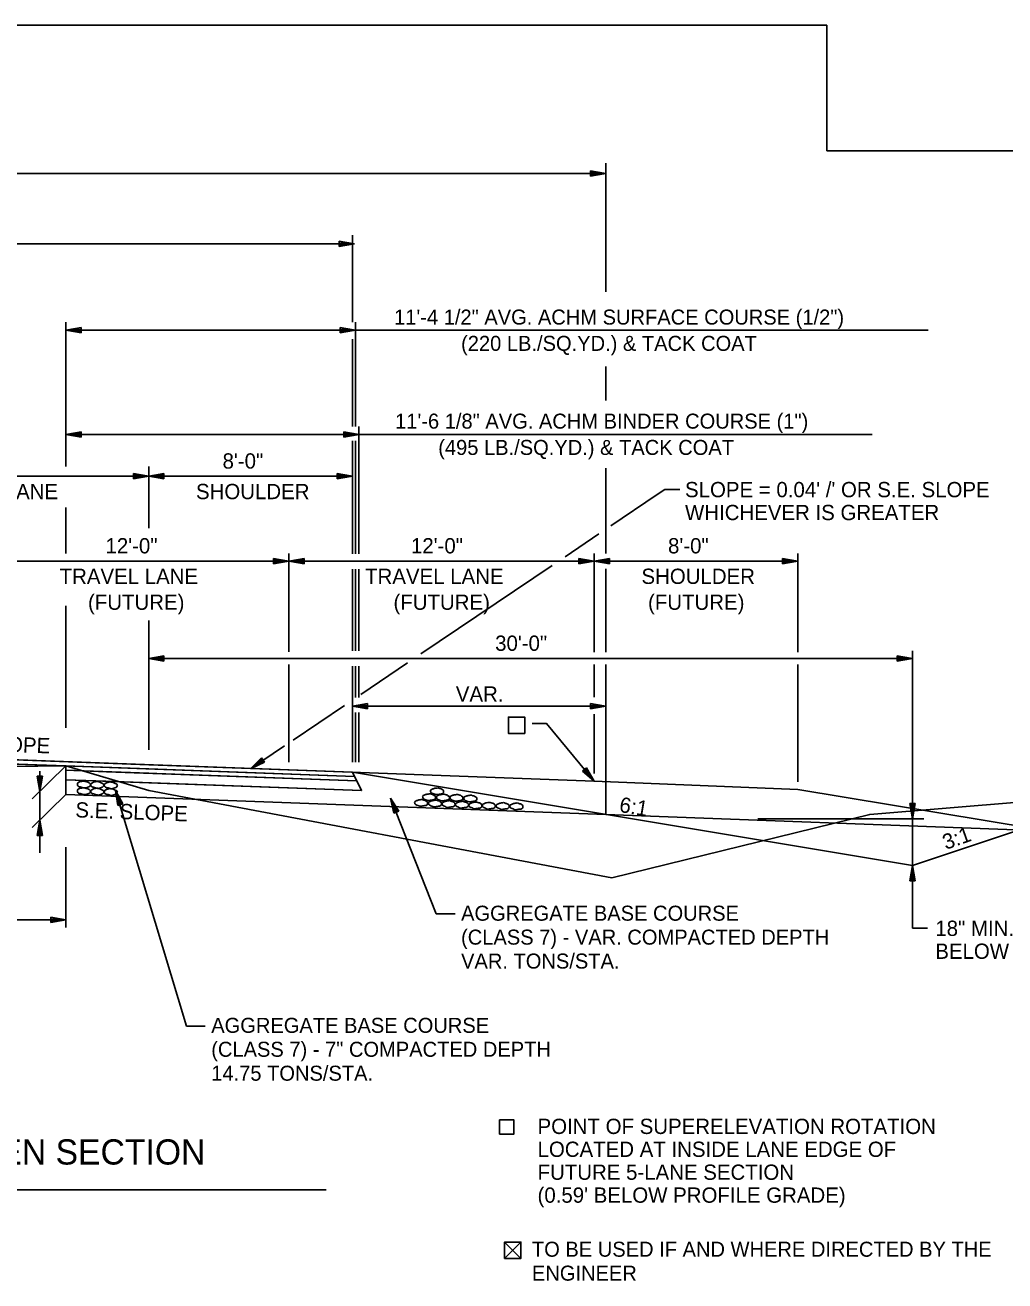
# Model space of a CAD drawing. Extents: x 1461846 to 1462006, y 1686171 to 1686805.
# Drawn here: x 1461933.27 to 1461971.75, y 1686623.62 to 1686672.94 of the extents above; entities that cross this region are included whole.
import ezdxf

# ---------------------------------------------------------------- set-up
doc = ezdxf.new("R2010")
doc.units = 0
for name, color, linetype in [('1', 7, 'Continuous'), ('10', 7, 'Continuous'), ('12', 7, 'Continuous'), ('19', 7, 'Continuous'), ('20', 7, 'Continuous'), ('3', 7, 'Continuous'), ('42', 7, 'Continuous'), ('Level 9', 7, 'Continuous'), ('R_Draft', 7, 'Continuous')]:
    doc.layers.add(name, color=color, linetype=linetype)

# ---------------------------------------------------------------- blocks, each defined once
blk = doc.blocks.new('ROCKS')
at = {"layer": '1'}
blk.add_spline([(0.013, 0.06), (0.053, 0.053), (0.107, 0.033), (0.133, 0.013), (0.133, -0.007), (0.12, -0.033), (0.107, -0.04), (0.073, -0.053), (0.033, -0.067), (0.013, -0.067), (-0.02, -0.06), (-0.06, -0.053), (-0.087, -0.047), (-0.113, -0.02), (-0.113, -0.007), (-0.107, 0.02), (-0.087, 0.033), (-0.067, 0.047), (-0.033, 0.053), (-0.02, 0.06), (0.013, 0.06)], degree=3, dxfattribs=at)

msp = doc.modelspace()

# ---------------------------------------------------------------- linework, layer by layer
at = {"layer": '10'}
for p, q in [((1461964.759, 1686672.939), (1461846.353, 1686672.939)), ((1461964.759, 1686667.999), (1461964.759, 1686672.939)), ((1461984.339, 1686667.999), (1461964.759, 1686667.999)), ((1461952.102, 1686625.138), (1461952.743, 1686624.497)), ((1461952.743, 1686625.138), (1461952.102, 1686624.497))]:
    msp.add_line(p, q, dxfattribs=at)
msp.add_lwpolyline([(1461952.253, 1686645.118), (1461952.894, 1686645.118), (1461952.894, 1686645.76), (1461952.253, 1686645.76)], close=True, dxfattribs=at)
for points in [[(1461951.906, 1686629.38), (1461951.906, 1686629.94), (1461952.466, 1686629.94), (1461952.466, 1686629.38), (1461951.906, 1686629.38)], [(1461952.495, 1686624.497), (1461952.743, 1686624.497), (1461952.743, 1686625.138), (1461952.102, 1686625.138), (1461952.102, 1686624.497), (1461952.483, 1686624.497)]]:
    msp.add_lwpolyline(points, dxfattribs=at)
at = {"layer": '19'}
for p, q in [((1461958.101, 1686654.5), (1461956.279, 1686653.272)), ((1461958.391, 1686654.696), (1461958.101, 1686654.5)), ((1461958.991, 1686654.696), (1461958.391, 1686654.696)), ((1461955.807, 1686652.955), (1461954.481, 1686652.06)), ((1461953.968, 1686651.715), (1461948.817, 1686648.242)), ((1461938.121, 1686648.063), (1461938.721, 1686648.168)), ((1461968.121, 1686648.063), (1461938.121, 1686648.063)), ((1461938.721, 1686647.958), (1461938.121, 1686648.063)), ((1461938.281, 1686648.078), (1461938.721, 1686648.113)), ((1461938.721, 1686648.008), (1461938.281, 1686648.048)), ((1461938.721, 1686648.168), (1461938.721, 1686647.958)), ((1461948.293, 1686647.889), (1461946.448, 1686646.645)), ((1461967.521, 1686647.958), (1461967.521, 1686648.168)), ((1461967.521, 1686648.168), (1461968.121, 1686648.063)), ((1461967.521, 1686648.113), (1461967.961, 1686648.078)), ((1461968.121, 1686648.063), (1461967.521, 1686647.958)), ((1461967.961, 1686648.048), (1461967.521, 1686648.008)), ((1461945.809, 1686646.214), (1461943.796, 1686644.858)), ((1461943.461, 1686644.632), (1461942.121, 1686643.728)), ((1461938.121, 1686643.888), (1461926.121, 1686644.332)), ((1461938.121, 1686643.722), (1461926.121, 1686644.166)), ((1461942.121, 1686643.728), (1461942.553, 1686644.157)), ((1461942.673, 1686643.985), (1461942.121, 1686643.728)), ((1461942.244, 1686643.832), (1461942.582, 1686644.116)), ((1461942.642, 1686644.03), (1461942.261, 1686643.807)), ((1461942.553, 1686644.157), (1461942.673, 1686643.985)), ((1461933.952, 1686643.44), (1461933.742, 1686643.44)), ((1461933.742, 1686643.44), (1461933.847, 1686642.84)), ((1461933.797, 1686643.44), (1461933.832, 1686643)), ((1461933.847, 1686642.84), (1461933.952, 1686643.44)), ((1461933.862, 1686643), (1461933.902, 1686643.44)), ((1461938.121, 1686643.722), (1461934.121, 1686643.87)), ((1461934.871, 1686642.717), (1461934.871, 1686643.842)), ((1461938.121, 1686643.555), (1461934.871, 1686643.675)), ((1461934.871, 1686643.675), (1461934.871, 1686643.3)), ((1461938.121, 1686643.888), (1461946.121, 1686643.592)), ((1461938.121, 1686643.722), (1461946.206, 1686643.422)), ((1461938.121, 1686643.555), (1461938.291, 1686643.549)), ((1461938.291, 1686643.549), (1461946.291, 1686643.253)), ((1461946.121, 1686643.592), (1461968.121, 1686639.926)), ((1461946.121, 1686643.592), (1461946.482, 1686642.871)), ((1461955.323, 1686643.772), (1461955.161, 1686643.639)), ((1461955.161, 1686643.639), (1461955.621, 1686643.241)), ((1461955.199, 1686643.666), (1461955.508, 1686643.356)), ((1461955.529, 1686643.37), (1461955.284, 1686643.734)), ((1461955.621, 1686643.241), (1461955.323, 1686643.772)), ((1461938.121, 1686643.18), (1461934.871, 1686643.3)), ((1461938.121, 1686643.18), (1461938.482, 1686643.167)), ((1461938.482, 1686643.167), (1461946.482, 1686642.871)), ((1461946.482, 1686642.871), (1461946.291, 1686643.253)), ((1461946.291, 1686643.253), (1461946.291, 1686643.253)), ((1461963.621, 1686642.921), (1461955.621, 1686643.241)), ((1461985.621, 1686639.254), (1461963.621, 1686642.921)), ((1461934.871, 1686642.717), (1461956.082, 1686641.932)), ((1461939.601, 1686633.623), (1461936.813, 1686642.882)), ((1461936.906, 1686642.282), (1461936.813, 1686642.882)), ((1461936.813, 1686642.882), (1461937.105, 1686642.347)), ((1461936.953, 1686642.298), (1461936.849, 1686642.726)), ((1461936.876, 1686642.736), (1461937.053, 1686642.333)), ((1461946.482, 1686642.871), (1461946.482, 1686642.871)), ((1461949.416, 1686638.029), (1461947.625, 1686642.581)), ((1461947.746, 1686641.986), (1461947.625, 1686642.581)), ((1461947.625, 1686642.581), (1461947.941, 1686642.061)), ((1461947.792, 1686642.005), (1461947.668, 1686642.427)), ((1461947.694, 1686642.438), (1461947.89, 1686642.044)), ((1461975.9, 1686642.519), (1461968.121, 1686639.926)), ((1461937.105, 1686642.347), (1461936.906, 1686642.282)), ((1461947.941, 1686642.061), (1461947.746, 1686641.986)), ((1461956.082, 1686641.932), (1461973.397, 1686641.291)), ((1461968.226, 1686642.37), (1461968.016, 1686642.37)), ((1461968.016, 1686642.37), (1461968.121, 1686641.77)), ((1461968.066, 1686642.37), (1461968.106, 1686641.93)), ((1461968.121, 1686641.77), (1461968.226, 1686642.37)), ((1461968.136, 1686641.93), (1461968.171, 1686642.37)), ((1461933.847, 1686641.715), (1461933.742, 1686641.115)), ((1461933.832, 1686641.555), (1461933.792, 1686641.115)), ((1461933.952, 1686641.115), (1461933.847, 1686641.715)), ((1461933.897, 1686641.115), (1461933.862, 1686641.555)), ((1461962.045, 1686641.77), (1461968.574, 1686641.77)), ((1461933.742, 1686641.115), (1461933.952, 1686641.115)), ((1461968.121, 1686639.926), (1461968.016, 1686639.326)), ((1461968.106, 1686639.766), (1461968.071, 1686639.326)), ((1461968.226, 1686639.326), (1461968.121, 1686639.926)), ((1461968.176, 1686639.326), (1461968.136, 1686639.766)), ((1461968.016, 1686639.326), (1461968.226, 1686639.326)), ((1461950.153, 1686638.029), (1461949.416, 1686638.029)), ((1461968.721, 1686637.465), (1461968.121, 1686637.465)), ((1461940.338, 1686633.623), (1461939.601, 1686633.623))]:
    msp.add_line(p, q, dxfattribs=at)
for points in [[(1461955.621, 1686643.241), (1461896.621, 1686645.424)], [(1461946.291, 1686643.253), (1461946.291, 1686643.253), (1461946.291, 1686643.253), (1461936.456, 1686643.616), (1461934.871, 1686643.675)], [(1461934.871, 1686643.3), (1461936.434, 1686643.242), (1461946.482, 1686642.871), (1461946.482, 1686642.871), (1461946.482, 1686642.871)]]:
    msp.add_lwpolyline(points, dxfattribs=at)
for points in [[(1461906.039, 1686644.909), (1461909.845, 1686644.768), (1461946.206, 1686643.422), (1461946.206, 1686643.422), (1461946.206, 1686643.422), (1461946.121, 1686643.592), (1461946.121, 1686643.592), (1461946.121, 1686643.592), (1461909.898, 1686644.932), (1461906.121, 1686645.072)], [(1461946.291, 1686643.253), (1461946.291, 1686643.253), (1461934.871, 1686643.675), (1461934.871, 1686643.675), (1461934.871, 1686643.675), (1461934.871, 1686643.842), (1461934.871, 1686643.842), (1461934.871, 1686643.842), (1461946.206, 1686643.422), (1461946.206, 1686643.422)]]:
    msp.add_lwpolyline(points, close=True, dxfattribs=at)
at = {"layer": '20'}
for p, q in [((1461895.93, 1686667.113), (1461956.082, 1686667.113)), ((1461955.482, 1686667.218), (1461955.482, 1686667.008)), ((1461956.082, 1686667.113), (1461955.482, 1686667.218)), ((1461955.922, 1686667.128), (1461955.482, 1686667.163)), ((1461955.482, 1686667.008), (1461956.082, 1686667.113)), ((1461955.482, 1686667.058), (1461955.922, 1686667.098)), ((1461956.082, 1686662.469), (1461956.082, 1686667.516)), ((1461946.121, 1686661.271), (1461946.121, 1686664.695)), ((1461906.121, 1686664.343), (1461946.206, 1686664.343)), ((1461945.606, 1686664.448), (1461945.606, 1686664.238)), ((1461946.206, 1686664.343), (1461945.606, 1686664.448)), ((1461946.046, 1686664.358), (1461945.606, 1686664.393)), ((1461945.606, 1686664.238), (1461946.206, 1686664.343)), ((1461945.606, 1686664.288), (1461946.046, 1686664.328)), ((1461934.871, 1686655.6), (1461934.871, 1686661.271)), ((1461946.246, 1686657.178), (1461946.246, 1686661.271)), ((1461935.471, 1686661.057), (1461934.871, 1686660.952)), ((1461934.871, 1686660.952), (1461935.471, 1686660.847)), ((1461934.871, 1686660.952), (1461946.246, 1686660.952)), ((1461935.471, 1686661.002), (1461935.031, 1686660.967)), ((1461935.031, 1686660.937), (1461935.471, 1686660.897)), ((1461935.471, 1686660.847), (1461935.471, 1686661.057)), ((1461945.646, 1686661.057), (1461945.646, 1686660.847)), ((1461946.246, 1686660.952), (1461945.646, 1686661.057)), ((1461946.086, 1686660.967), (1461945.646, 1686661.002)), ((1461945.646, 1686660.847), (1461946.246, 1686660.952)), ((1461945.646, 1686660.897), (1461946.086, 1686660.937)), ((1461946.246, 1686660.952), (1461968.746, 1686660.952)), ((1461946.121, 1686657.178), (1461946.121, 1686660.607)), ((1461956.082, 1686658.191), (1461956.082, 1686659.535)), ((1461935.471, 1686656.964), (1461934.871, 1686656.859)), ((1461934.871, 1686656.859), (1461946.381, 1686656.859)), ((1461934.871, 1686656.859), (1461935.471, 1686656.754)), ((1461935.471, 1686656.909), (1461935.031, 1686656.874)), ((1461935.031, 1686656.844), (1461935.471, 1686656.804)), ((1461935.471, 1686656.754), (1461935.471, 1686656.964)), ((1461945.787, 1686656.964), (1461945.787, 1686656.754)), ((1461946.387, 1686656.859), (1461945.787, 1686656.964)), ((1461946.227, 1686656.874), (1461945.787, 1686656.909)), ((1461945.787, 1686656.754), (1461946.387, 1686656.859)), ((1461945.787, 1686656.804), (1461946.227, 1686656.844)), ((1461946.381, 1686654.851), (1461946.381, 1686657.178)), ((1461946.381, 1686656.859), (1461966.535, 1686656.859)), ((1461946.121, 1686652.177), (1461946.121, 1686656.617)), ((1461946.246, 1686654.851), (1461946.246, 1686656.617)), ((1461937.521, 1686655.115), (1461937.521, 1686655.325)), ((1461937.521, 1686655.325), (1461938.121, 1686655.22)), ((1461937.521, 1686655.27), (1461937.961, 1686655.235)), ((1461938.121, 1686653.183), (1461938.121, 1686655.6)), ((1461938.121, 1686655.22), (1461938.721, 1686655.325)), ((1461938.281, 1686655.235), (1461938.721, 1686655.27)), ((1461938.721, 1686655.325), (1461938.721, 1686655.115)), ((1461945.521, 1686655.115), (1461945.521, 1686655.325)), ((1461945.521, 1686655.325), (1461946.121, 1686655.22)), ((1461945.521, 1686655.27), (1461945.961, 1686655.235)), ((1461956.082, 1686652.19), (1461956.082, 1686655.536)), ((1461938.121, 1686655.22), (1461926.121, 1686655.22)), ((1461938.121, 1686655.22), (1461937.521, 1686655.115)), ((1461937.961, 1686655.205), (1461937.521, 1686655.165)), ((1461946.121, 1686655.22), (1461938.121, 1686655.22)), ((1461938.721, 1686655.115), (1461938.121, 1686655.22)), ((1461938.721, 1686655.165), (1461938.281, 1686655.205)), ((1461946.121, 1686655.22), (1461945.521, 1686655.115)), ((1461945.961, 1686655.205), (1461945.521, 1686655.165)), ((1461946.246, 1686652.177), (1461946.246, 1686654.851)), ((1461946.381, 1686652.177), (1461946.381, 1686654.851)), ((1461934.871, 1686652.19), (1461934.871, 1686653.997)), ((1461943.621, 1686651.89), (1461931.621, 1686651.89)), ((1461943.021, 1686651.995), (1461943.021, 1686651.785)), ((1461943.621, 1686651.89), (1461943.021, 1686651.995)), ((1461943.461, 1686651.905), (1461943.021, 1686651.94)), ((1461943.021, 1686651.785), (1461943.621, 1686651.89)), ((1461943.021, 1686651.835), (1461943.461, 1686651.875)), ((1461943.621, 1686648.324), (1461943.621, 1686652.19)), ((1461943.621, 1686651.89), (1461944.221, 1686651.995)), ((1461955.621, 1686651.89), (1461943.621, 1686651.89)), ((1461944.221, 1686651.785), (1461943.621, 1686651.89)), ((1461943.781, 1686651.905), (1461944.221, 1686651.94)), ((1461944.221, 1686651.835), (1461943.781, 1686651.875)), ((1461944.221, 1686651.995), (1461944.221, 1686651.785)), ((1461955.021, 1686651.785), (1461955.021, 1686651.995)), ((1461955.021, 1686651.995), (1461955.621, 1686651.89)), ((1461955.021, 1686651.94), (1461955.461, 1686651.905)), ((1461955.621, 1686651.89), (1461955.021, 1686651.785)), ((1461955.461, 1686651.875), (1461955.021, 1686651.835)), ((1461955.621, 1686648.317), (1461955.621, 1686652.19)), ((1461955.621, 1686651.89), (1461956.221, 1686651.995)), ((1461963.621, 1686651.89), (1461955.621, 1686651.89)), ((1461956.221, 1686651.785), (1461955.621, 1686651.89)), ((1461955.781, 1686651.905), (1461956.221, 1686651.94)), ((1461956.221, 1686651.835), (1461955.781, 1686651.875)), ((1461956.221, 1686651.995), (1461956.221, 1686651.785)), ((1461963.021, 1686651.785), (1461963.021, 1686651.995)), ((1461963.021, 1686651.995), (1461963.621, 1686651.89)), ((1461963.021, 1686651.94), (1461963.461, 1686651.905)), ((1461963.621, 1686651.89), (1461963.021, 1686651.785)), ((1461963.461, 1686651.875), (1461963.021, 1686651.835)), ((1461963.621, 1686648.317), (1461963.621, 1686652.19)), ((1461946.121, 1686648.363), (1461946.121, 1686651.569)), ((1461946.246, 1686648.363), (1461946.246, 1686651.569)), ((1461946.381, 1686648.363), (1461946.381, 1686651.569)), ((1461956.082, 1686648.317), (1461956.082, 1686651.587)), ((1461934.871, 1686645.341), (1461934.871, 1686650.132)), ((1461938.121, 1686644.473), (1461938.121, 1686649.556)), ((1461968.121, 1686637.465), (1461968.121, 1686648.363)), ((1461943.621, 1686643.985), (1461943.621, 1686647.82)), ((1461946.121, 1686643.985), (1461946.121, 1686647.763)), ((1461946.246, 1686646.534), (1461946.246, 1686647.763)), ((1461946.381, 1686646.534), (1461946.381, 1686647.763)), ((1461955.621, 1686646.542), (1461955.621, 1686647.82)), ((1461956.082, 1686641.932), (1461956.082, 1686647.82)), ((1461963.621, 1686643.221), (1461963.621, 1686647.82)), ((1461946.721, 1686646.29), (1461946.121, 1686646.185)), ((1461946.121, 1686646.185), (1461956.082, 1686646.185)), ((1461946.121, 1686646.185), (1461946.721, 1686646.08)), ((1461946.246, 1686643.985), (1461946.246, 1686645.937)), ((1461946.721, 1686646.235), (1461946.281, 1686646.2)), ((1461946.281, 1686646.17), (1461946.721, 1686646.13)), ((1461946.381, 1686643.985), (1461946.381, 1686645.937)), ((1461946.721, 1686646.08), (1461946.721, 1686646.29)), ((1461955.482, 1686646.29), (1461955.482, 1686646.08)), ((1461956.082, 1686646.185), (1461955.482, 1686646.29)), ((1461955.922, 1686646.2), (1461955.482, 1686646.235)), ((1461955.482, 1686646.08), (1461956.082, 1686646.185)), ((1461955.482, 1686646.13), (1461955.922, 1686646.17)), ((1461955.621, 1686643.541), (1461955.621, 1686645.881)), ((1461934.871, 1686643.842), (1461933.548, 1686642.547)), ((1461934.871, 1686642.717), (1461933.548, 1686641.422))]:
    msp.add_line(p, q, dxfattribs=at)
msp.add_lwpolyline([(1461933.847, 1686643.631), (1461933.847, 1686640.434)], dxfattribs=at)
at = {"layer": '3'}
msp.add_line((1461907.149, 1686627.199), (1461945.094, 1686627.199), dxfattribs=at)
at = {"layer": 'Level 9'}
msp.add_lwpolyline([(1461953.178, 1686645.505), (1461953.748, 1686645.505), (1461955.621, 1686643.241)], dxfattribs=at)
at = {"layer": 'R_Draft'}
for p, q in [((1461934.871, 1686637.493), (1461934.871, 1686640.646)), ((1461934.871, 1686637.793), (1461910.871, 1686637.793)), ((1461934.271, 1686637.688), (1461934.271, 1686637.898)), ((1461934.271, 1686637.898), (1461934.871, 1686637.793)), ((1461934.271, 1686637.843), (1461934.711, 1686637.808)), ((1461934.871, 1686637.793), (1461934.271, 1686637.688)), ((1461934.711, 1686637.778), (1461934.271, 1686637.738))]:
    msp.add_line(p, q, dxfattribs=at)
for points in [[(1461952.894, 1686645.118), (1461952.894, 1686645.76), (1461952.253, 1686645.76), (1461952.253, 1686645.118), (1461952.894, 1686645.118)], [(1462000.252, 1686643.294), (1461985.479, 1686642.773), (1461972.442, 1686642.427), (1461966.445, 1686641.94), (1461956.315, 1686639.45), (1461938.121, 1686642.877), (1461934.871, 1686643.842), (1461929.37, 1686643.781), (1461912.792, 1686644.39), (1461910.871, 1686644.73), (1461906.121, 1686644.095), (1461890.249, 1686639.689)]]:
    msp.add_lwpolyline(points, dxfattribs=at)

# ---------------------------------------------------------------- block references
at = {"layer": '19'}
for p, xscale, yscale, rotation in [((1461935.553, 1686642.857), 2.0611362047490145, 2.0611362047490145, -3.7637562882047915), ((1461935.554, 1686643.119), 2.0611362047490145, 2.0611362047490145, -3.7637562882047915), ((1461936.082, 1686643.103), 2.0611362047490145, 2.0611362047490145, -3.7637562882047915), ((1461936.082, 1686642.841), 2.0611362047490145, 2.0611362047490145, -3.7637562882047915), ((1461936.612, 1686643.088), 2.0611362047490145, 2.0611362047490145, -3.7637562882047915), ((1461936.612, 1686642.826), 2.0611362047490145, 2.0611362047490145, -3.7637562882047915), ((1461949.469, 1686642.851), 2.061136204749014, -2.061136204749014, 178.63717054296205), ((1461948.845, 1686642.394), 2.061136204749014, -2.061136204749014, 178.63717054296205), ((1461949.158, 1686642.62), 2.061136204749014, -2.061136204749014, 178.63717054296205), ((1461949.39, 1686642.372), 2.061136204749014, -2.061136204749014, 178.63717054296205), ((1461949.7, 1686642.607), 2.061136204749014, -2.061136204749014, 178.63717054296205), ((1461949.922, 1686642.35), 2.061136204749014, -2.061136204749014, 178.63717054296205), ((1461950.233, 1686642.594), 2.061136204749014, -2.061136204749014, 178.63717054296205), ((1461950.446, 1686642.324), 2.061136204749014, -2.061136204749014, 178.63717054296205), ((1461950.776, 1686642.566), 2.061136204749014, -2.061136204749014, 178.63717054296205), ((1461950.977, 1686642.297), 2.061136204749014, -2.061136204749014, 178.63717054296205), ((1461951.503, 1686642.284), 2.061136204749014, -2.061136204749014, 178.63717054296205), ((1461952.047, 1686642.272), 2.061136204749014, -2.061136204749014, 178.63717054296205), ((1461952.586, 1686642.259), 2.061136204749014, -2.061136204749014, 178.63717054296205)]:
    msp.add_blockref('ROCKS', p, dxfattribs=dict(at, xscale=xscale, yscale=yscale, rotation=rotation))

# ---------------------------------------------------------------- texts
at = {"layer": '10'}
for s, p in [('12\'-0"', (1461936.423, 1686652.19)), ('12\'-0"', (1461948.423, 1686652.19)), ('8\'-0"', (1461958.522, 1686652.19)), ('TRAVEL LANE', (1461934.621, 1686650.99)), ('TRAVEL LANE', (1461946.621, 1686650.99)), ('SHOULDER', (1461957.478, 1686650.99)), ('(FUTURE)', (1461935.736, 1686649.974)), ('(FUTURE)', (1461947.736, 1686649.974)), ('(FUTURE)', (1461957.736, 1686649.974))]:
    msp.add_text(s, height=0.6, dxfattribs=at).set_placement(p)
for s, height, p in [('TO BE USED IF AND WHERE DIRECTED BY THE ', 0.59001, (1461953.175, 1686624.565)), ('ENGINEER', 0.59, (1461953.175, 1686623.625))]:
    msp.add_text(s, height=height, rotation=360, dxfattribs=at).set_placement(p)
at = {"layer": '12'}
msp.add_text('SUPERELEVATED NOTCH AND WIDEN SECTION', height=0.98999, rotation=359.9954, dxfattribs=at).set_placement((1461909.6, 1686628.188))
at = {"layer": '19'}
for s, p in [('AGGREGATE BASE COURSE', (1461950.391, 1686637.763)), ('(CLASS 7) - VAR. COMPACTED DEPTH', (1461950.391, 1686636.823)), ('VAR. TONS/STA.', (1461950.391, 1686635.883)), ('AGGREGATE BASE COURSE', (1461940.577, 1686633.358)), ('(CLASS 7) - 7" COMPACTED DEPTH', (1461940.577, 1686632.418)), ('14.75 TONS/STA.', (1461940.577, 1686631.478))]:
    msp.add_text(s, height=0.59001, rotation=360, dxfattribs=at).set_placement(p)
at = {"layer": '42'}
for s, p in [('11\'-4 1/2" AVG. ACHM SURFACE COURSE (1/2")', (1461947.76, 1686661.177)), ('(220 LB./SQ.YD.) & TACK COAT', (1461950.392, 1686660.145)), ('11\'-6 1/8" AVG. ACHM BINDER COURSE (1")', (1461947.8, 1686657.09)), ('(495 LB./SQ.YD.) & TACK COAT', (1461949.494, 1686656.057))]:
    msp.add_text(s, height=0.59001, rotation=360, dxfattribs=at).set_placement(p)
at = {"layer": 'R_Draft'}
for s, p in [('8\'-0"', (1461941.022, 1686655.52)), ('TRAVEL LANE', (1461929.121, 1686654.32)), ('SHOULDER', (1461939.978, 1686654.32)), ("SLOPE = 0.04' /' OR S.E. SLOPE", (1461959.189, 1686654.396)), ('WHICHEVER IS GREATER', (1461959.189, 1686653.496)), ('30\'-0"', (1461951.729, 1686648.363)), ('18" MIN. DEPTH', (1461969.021, 1686637.165)), ('BELOW SUBGRADE', (1461969.021, 1686636.265))]:
    msp.add_text(s, height=0.6, dxfattribs=at).set_placement(p)
for s, rotation, p in [('VAR.', 360, (1461950.185, 1686646.368)), ('S.E. SLOPE', 357.881, (1461929.828, 1686644.495)), ('S.E. SLOPE', 357.881, (1461935.231, 1686641.823)), ('6:1', 350.5377, (1461956.579, 1686642.04)), ('3:1', 19.5057, (1461969.433, 1686640.541)), ('POINT OF SUPERELEVATION ROTATION', 359.9954, (1461953.396, 1686629.386)), ('LOCATED AT INSIDE LANE EDGE OF', 359.9954, (1461953.396, 1686628.486)), ('FUTURE 5-LANE SECTION', 359.9954, (1461953.396, 1686627.586)), ("(0.59' BELOW PROFILE GRADE)", 359.9954, (1461953.396, 1686626.686))]:
    msp.add_text(s, height=0.6, rotation=rotation, dxfattribs=at).set_placement(p)

doc.saveas('drawing.dxf')
